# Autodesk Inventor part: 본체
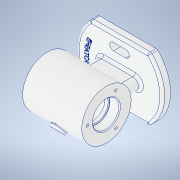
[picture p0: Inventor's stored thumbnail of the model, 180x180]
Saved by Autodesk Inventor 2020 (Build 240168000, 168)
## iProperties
Created: 2022-02
Part Number: 본체
Material: 알루미늄 6061
Document SubType Name: Modeling
Designer: 602-08
Density: 2.7 g/cm^3
Appearance: 알루미늄 - 평지
Mass: 495.247 g
Surface Area: 489.75 cm^2
Volume: 183.425 cm^3
Author: 602-08
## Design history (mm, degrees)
sketch "스케치1"
  geometry: L1 (-52, 38)-(52, 38); L2 (52, 38)-(52, -38); L3 (52, -38)-(-52, -38); L4 (-52, -38)-(-52, 38); L5 (-52, 38)-(52, -38); L6 (52, 38)-(-52, -38); C1 r 52 at (0, 0); 5 further points
  constraints: 12 end point, 2 midpoint, 2 parallel, 1 centre point, 1 coincident, 1 horizontal, 1 perpendicular, 1 tangent
  dimensions: "d0" = 104 diameter of C1; "d1" = 76 distance of L1.end L2.end
extrude "돌출1" new body sketch "스케치1" distance "d2" = 10; taper "d3" = 0 deg
sketch "스케치2"
  geometry: L1 (38, 0)-(-38, 0) reference; C1 r 30 at (0, 62); 2 further points
  constraints: 1 centre point, 1 midpoint, 1 vertical alignment
  dimensions: "d4" = 60 diameter of C1; "d5" = 62 distance from line of L1 C1.centre
extrude "돌출2" join sketch "스케치2" stored distance "d6" = 72; taper "d7" = 0 deg
sketch "스케치3"
  geometry: L1 (-19, 0)-(19, 0); L2 (-19, -7)-(19, -7); L3 (19, 7)-(-19, 7); A1 r 7 centre (-19, 0) between (-19, 7) and (-19, -7); A2 r 7 centre (19, 0) between (19, -7) and (19, 7); 2 further points
  constraints: 8 end point, 4 point on circle, 4 tangent, 2 centre point, 2 coincident, 1 horizontal, 1 midpoint, 1 parallel
  dimensions: "d8" = 14 distance between parallel lines of L3 L2; "d9" = 38 distance of L1.end L1.start
extrude "돌출3" join sketch "스케치3" stored distance "d10" = 72; taper "d11" = 0 deg
sketch "스케치4"
  geometry: L1 (36, 32)-(36, 92) reference; L2 (36, 62)-(-36, 62); L3 (-36, 92)-(-36, 32) reference; L4 (36, 62)-(36, 78); L5 (24, 78)-(24, 76); L6 (24, 76)-(20, 76); L7 (20, 76)-(20, 87); L8 (20, 87)-(-20, 87); L9 (-20, 87)-(-20, 76); L10 (-20, 76)-(-24, 76); L11 (-24, 76)-(-24, 78); L12 (-24, 78)-(-36, 78); L13 (-36, 62)-(-36, 78); L14 (36, 78)-(24, 78); 1 further point
  constraints: 24 end point, 8 perpendicular, 4 point on line, 2 midpoint, 1 vertical
  dimensions: "d12" = 32 diameter of L14 L2; "d13" = 28 diameter of L6 L2; "d14" = 40 distance between parallel lines of L9 L7; "d15" = 50 diameter of L8 L2; "d16" = 12 distance between parallel lines of L4 L5; "d17" = 12 distance between parallel lines of L3 L11; "d18" = 32 diameter of L12 L2; "d19" = 4 distance between parallel lines of L5 L7
revolve "회전1" sketch "스케치4" stored, may be unused: angle "d20" = 90 deg
sketch "스케치5" dims "d28" = 46
  geometry: L1 (0, 0)-(23, 0); C1 r 16 at (0, 0) reference; 2 further points
  constraints: 2 coincident, 2 end point, 1 horizontal, 1 horizontal alignment, 2 other
hole "구멍1" sketch "스케치5" at (23, 0) diameter "d21" = 3.242; stored, may be unused: countersink angle "d25" = 90 deg, drill point angle "d27" = 118 deg; dims "d22" = 8, "d23" = 4, "d24" = 2, "d26" = 10
sketch "스케치6"
  geometry: C1 r 42.5 at (0, 0); 1 further point
  constraints: 1 centre point, 1 coincident, 1 other
  dimensions: "d32" = 85 diameter of C1
feature "엠보싱1" sketch "스케치6" dims "d0" = 104, "d1" = 76, "d8" = 14, "d9" = 38, "d33" = 0.5, "d34" = 0
fillet "모깎기1" dims "d35" = 0.3, "d36" = 3
sketch "스케치7"
  geometry: L1 (-7.5, -24)-(7.5, -24); L2 (-7.5, -28.5)-(7.5, -28.5); L3 (7.5, -19.5)-(-7.5, -19.5); L4 (52, 0)-(-52, 0); L5 (-7.5, 24)-(7.5, 24); L6 (-7.5, 28.5)-(7.5, 28.5); L7 (7.5, 19.5)-(-7.5, 19.5); A1 r 4.5 centre (-7.5, -24) between (-7.5, -19.5) and (-7.5, -28.5); A2 r 4.5 centre (7.5, -24) between (7.5, -28.5) and (7.5, -19.5); A3 r 52 centre (0, 0) between (35.496, -38) and (35.496, 38) reference; A4 r 52 centre (0, 0) between (-35.496, 38) and (-35.496, -38) reference; A5 r 4.5 centre (-7.5, 24) between (-7.5, 28.5) and (-7.5, 19.5); A6 r 4.5 centre (7.5, 24) between (7.5, 19.5) and (7.5, 28.5); 3 further points
  constraints: 18 end point, 10 point on circle, 7 symmetric about line, 4 centre point, 4 tangent, 2 horizontal, 1 midpoint, 1 parallel, 1 vertical alignment, 2 other
  dimensions: "d37" = 15 distance of L1.start L1.end; "d38" = 9 distance between parallel lines of L2 L3; "d39" = 24 distance of point (0, 0) point (0, -24)
extrude "돌출4" cut sketch "스케치7" distance "d40" = 10; taper "d41" = 0 deg
fillet "모깎기2" dims "d42" = 3
fillet "모깎기3" dims "d43" = 3
chamfer "모따기1" distance "d44" = 1; stored, may be unused: second distance "d45" = 2, angle "d46" = 45 deg
node "작업 평면3"
  node "작업 평면2"
sketch "스케치8"
  geometry: L1 (-36, 30)-(-36, -30) reference; L2 (-36, 30)-(-36, -30) reference; L3 (36, -30)-(36, 30) reference; L4 (-19, -13.788)-(19, -13.788) reference; L5 (19, -26.644)-(-19, -26.644) reference; L6 (-36, 30)-(36, 30) reference; L7 (0, 30)-(0, -30); L8 (-36, 0)-(36, 0); L9 (36, -17)-(36, 17) reference; L10 (-36, 14.642)-(-36, 17.884) reference; C1 r 8 at (0, 0); 1 further point
  constraints: 4 end point, 4 midpoint, 3 vertical alignment, 1 centre point, 1 vertical
  dimensions: "d49" = 16 diameter of C1
extrude "돌출5" join sketch "스케치8" stored distance "d50" = 10; taper "d51" = 0 deg
sketch "스케치9"
  geometry: C1 r 8 at (0, 0) reference; 2 further points
  constraints: 1 coincident
hole "구멍2" sketch "스케치9" at (0, 0) diameter "d52" = 8; stored, may be unused: countersink angle "d56" = 90 deg, drill point angle "d58" = 118 deg; dims "d53" = 8, "d54" = 4, "d55" = 2, "d57" = 39.75
fillet "모깎기4" dims "d62" = 1
fillet "모깎기5" dims "d66" = 1
node "솔리드1"
pattern_circular "원형 패턴1" dims angle "d30" = 360 deg
mirror "미러1"
node "작업 평면1"
node "투영된 루프1"
feature "A9D066F2-1C7D-4E18-AEED-F7BC21143FA4" dims "d52" = 8, "d53" = 8, "d54" = 4, "d55" = 2, "d56" = 90 deg, "d57" = 39.75, "d58" = 118 deg
other parameters: "d47" = 62, "d48" = -33
